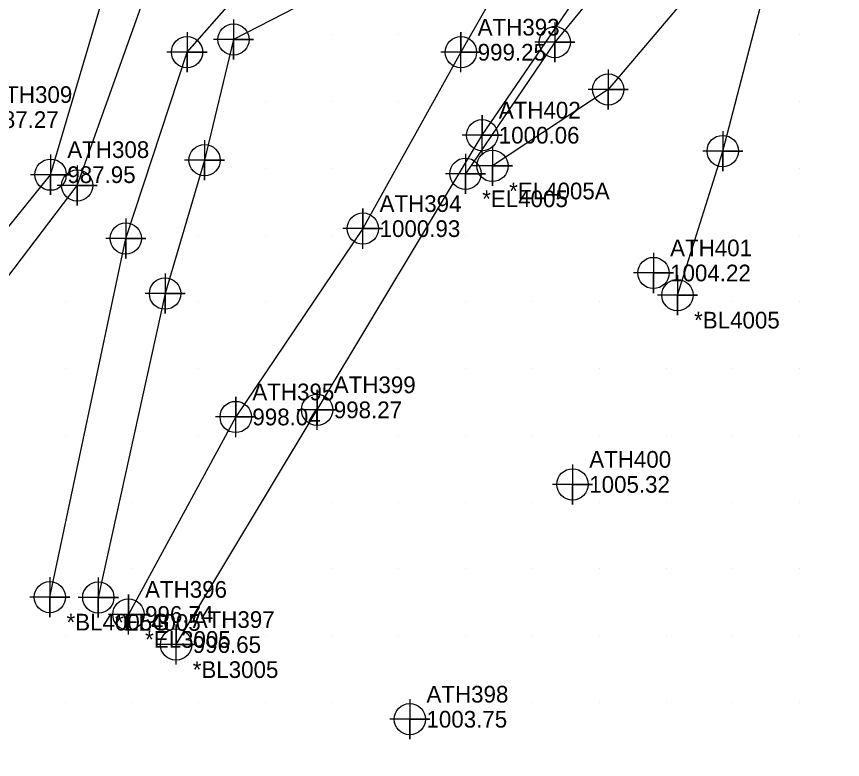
# Model space of a CAD drawing. Extents: x 1116680 to 1117499, y 661040 to 661703.
# Drawn here: x 1117062.7 to 1117186.4, y 661221.5 to 661332.7 of the extents above; entities that cross this region are included whole.
import ezdxf

# ---------------------------------------------------------------- set-up
doc = ezdxf.new("R2010")
doc.units = 0
for name, color, linetype in [('Exist DTM Breakline', 7, 'Continuous'), ('Exist DTM Breakline Cogo Comment', 7, 'Continuous'), ('Exist DTM Breakline Cogo Point CELL', 7, 'Continuous'), ('Exist DTM Drainline Cogo Elevation', 7, 'Continuous'), ('Exist DTM Drainline Cogo Number', 7, 'Continuous'), ('Exist DTM Drainline Cogo Point CELL', 7, 'Continuous'), ('Exist DTM QL2 LIDAR Elevation Point', 7, 'Continuous'), ('Exist DTM Regular Point CELL', 7, 'Continuous'), ('Exist DTM Regular Point Cogo Elevation', 7, 'Continuous'), ('Exist DTM Regular Point Cogo Number', 7, 'Continuous'), ('Exist DTM Regular Point Underwater Cogo Elevation', 7, 'Continuous'), ('Exist DTM Regular Point Underwater Cogo Number', 7, 'Continuous'), ('Exist Hydro Stream or Body of Water', 7, 'Continuous'), ('Exist Roads Soil', 7, 'Continuous'), ('Exist Roads Soil Cogo Comment', 7, 'Continuous'), ('Exist Roads Soil Cogo Elevation', 7, 'Continuous'), ('Exist Roads Soil Cogo Number', 7, 'Continuous'), ('Exist Roads Soil Cogo Point CELL', 7, 'Continuous')]:
    doc.layers.add(name, color=color, linetype=linetype)

msp = doc.modelspace()

# ---------------------------------------------------------------- linework, layer by layer
at = {"layer": 'Exist DTM Breakline'}
for points in [[(1117161.696, 661291.017), (1117168.482, 661312.597), (1117176.266, 661342.559), (1117182.941, 661374.652), (1117194.026, 661386.336), (1117220.943, 661405.14), (1117272.33, 661460.939), (1117291.277, 661496.211), (1117300.472, 661516.498), (1117320.583, 661567.148), (1117342.592, 661626.703), (1117356.346, 661660.105)], [(1117170.247, 661372.296), (1117153.034, 661340.751), (1117143.346, 661328.905), (1117129.964, 661309.196)], [(1117170.843, 661370.689), (1117163.366, 661336.06), (1117151.339, 661321.82), (1117133.997, 661310.363)], [(1117093.445, 661360.799), (1117137.626, 661368.708), (1117143.021, 661357.384), (1117121.473, 661342.844), (1117095.236, 661329.298), (1117090.897, 661311.231), (1117084.978, 661291.24), (1117074.985, 661245.735)], [(1117067.72, 661245.781), (1117079.092, 661299.504), (1117088.264, 661327.406), (1117096.09, 661336.305), (1117116.041, 661346.019), (1117139.594, 661357.628)], [(1117040.467, 661266.201), (1117071.81, 661307.445), (1117084.165, 661341.998)]]:
    msp.add_lwpolyline(points, dxfattribs=at)
at = {"layer": 'Exist DTM Breakline Cogo Point CELL'}
for points in [[(1117095.236, 661332.298), (1117095.236, 661326.298), (1117095.236, 661329.298), (1117098.236, 661329.298), (1117092.236, 661329.298)], [(1117143.346, 661331.905), (1117143.346, 661325.905), (1117143.346, 661328.905), (1117146.346, 661328.905), (1117140.346, 661328.905)], [(1117088.264, 661330.406), (1117088.264, 661324.406), (1117088.264, 661327.406), (1117091.264, 661327.406), (1117085.264, 661327.406)], [(1117151.339, 661324.82), (1117151.339, 661318.82), (1117151.339, 661321.82), (1117154.339, 661321.82), (1117148.339, 661321.82)], [(1117168.482, 661315.597), (1117168.482, 661309.597), (1117168.482, 661312.597), (1117171.482, 661312.597), (1117165.482, 661312.597)], [(1117090.897, 661314.231), (1117090.897, 661308.231), (1117090.897, 661311.231), (1117093.897, 661311.231), (1117087.897, 661311.231)], [(1117133.997, 661313.363), (1117133.997, 661307.363), (1117133.997, 661310.363), (1117136.997, 661310.363), (1117130.997, 661310.363)], [(1117129.964, 661312.196), (1117129.964, 661306.196), (1117129.964, 661309.196), (1117132.964, 661309.196), (1117126.964, 661309.196)], [(1117071.81, 661310.445), (1117071.81, 661304.445), (1117071.81, 661307.445), (1117074.81, 661307.445), (1117068.81, 661307.445)], [(1117079.092, 661302.504), (1117079.092, 661296.504), (1117079.092, 661299.504), (1117082.092, 661299.504), (1117076.092, 661299.504)], [(1117084.978, 661294.24), (1117084.978, 661288.24), (1117084.978, 661291.24), (1117087.978, 661291.24), (1117081.978, 661291.24)], [(1117161.696, 661294.017), (1117161.696, 661288.017), (1117161.696, 661291.017), (1117164.696, 661291.017), (1117158.696, 661291.017)], [(1117067.72, 661248.781), (1117067.72, 661242.781), (1117067.72, 661245.781), (1117070.72, 661245.781), (1117064.72, 661245.781)], [(1117074.985, 661248.735), (1117074.985, 661242.735), (1117074.985, 661245.735), (1117077.985, 661245.735), (1117071.985, 661245.735)]]:
    msp.add_lwpolyline(points, dxfattribs=at)
for centre in [(1117095.236, 661329.298), (1117143.346, 661328.905), (1117088.264, 661327.406), (1117151.339, 661321.82), (1117168.482, 661312.597), (1117090.897, 661311.231), (1117133.997, 661310.363), (1117129.964, 661309.196), (1117071.81, 661307.445), (1117079.092, 661299.504), (1117084.978, 661291.24), (1117161.696, 661291.017), (1117067.72, 661245.781), (1117074.985, 661245.735)]:
    msp.add_circle(centre, 2.344, dxfattribs=at)
at = {"layer": 'Exist DTM Drainline Cogo Point CELL'}
msp.add_lwpolyline([(1117067.842, 661312.057), (1117067.842, 661306.057), (1117067.842, 661309.057), (1117070.842, 661309.057), (1117064.842, 661309.057)], dxfattribs=at)
msp.add_circle((1117067.842, 661309.057), 2.344, dxfattribs=at)
at = {"layer": 'Exist DTM QL2 LIDAR Elevation Point'}
for p, q in [((1117110, 661330), (1117110, 661330)), ((1117120, 661330), (1117120, 661330)), ((1117180, 661330), (1117180, 661330)), ((1117100, 661320), (1117100, 661320)), ((1117110, 661320), (1117110, 661320)), ((1117120, 661320), (1117120, 661320)), ((1117180, 661320), (1117180, 661320)), ((1117080, 661310), (1117080, 661310)), ((1117100, 661310), (1117100, 661310)), ((1117110, 661310), (1117110, 661310)), ((1117180, 661310), (1117180, 661310)), ((1117090, 661300), (1117090, 661300)), ((1117100, 661300), (1117100, 661300)), ((1117110, 661300), (1117110, 661300)), ((1117130, 661300), (1117130, 661300)), ((1117170, 661300), (1117170, 661300)), ((1117180, 661300), (1117180, 661300)), ((1117070, 661290), (1117070, 661290)), ((1117090, 661290), (1117090, 661290)), ((1117100, 661290), (1117100, 661290)), ((1117130, 661290), (1117130, 661290)), ((1117140, 661290), (1117140, 661290)), ((1117150, 661290), (1117150, 661290)), ((1117170, 661290), (1117170, 661290)), ((1117180, 661290), (1117180, 661290)), ((1117070, 661280), (1117070, 661280)), ((1117090, 661280), (1117090, 661280)), ((1117120, 661280), (1117120, 661280)), ((1117130, 661280), (1117130, 661280)), ((1117140, 661280), (1117140, 661280)), ((1117150, 661280), (1117150, 661280)), ((1117160, 661280), (1117160, 661280)), ((1117170, 661280), (1117170, 661280)), ((1117180, 661280), (1117180, 661280)), ((1117070, 661270), (1117070, 661270)), ((1117090, 661270), (1117090, 661270)), ((1117120, 661270), (1117120, 661270)), ((1117130, 661270), (1117130, 661270)), ((1117140, 661270), (1117140, 661270)), ((1117150, 661270), (1117150, 661270)), ((1117160, 661270), (1117160, 661270)), ((1117170, 661270), (1117170, 661270)), ((1117180, 661270), (1117180, 661270)), ((1117080, 661260), (1117080, 661260)), ((1117110, 661260), (1117110, 661260)), ((1117120, 661260), (1117120, 661260)), ((1117130, 661260), (1117130, 661260)), ((1117140, 661260), (1117140, 661260)), ((1117150, 661260), (1117150, 661260)), ((1117160, 661260), (1117160, 661260)), ((1117170, 661260), (1117170, 661260)), ((1117180, 661260), (1117180, 661260)), ((1117080, 661250), (1117080, 661250)), ((1117110, 661250), (1117110, 661250)), ((1117120, 661250), (1117120, 661250)), ((1117130, 661250), (1117130, 661250)), ((1117140, 661250), (1117140, 661250)), ((1117150, 661250), (1117150, 661250)), ((1117160, 661250), (1117160, 661250)), ((1117170, 661250), (1117170, 661250)), ((1117180, 661250), (1117180, 661250)), ((1117070, 661240), (1117070, 661240)), ((1117100, 661240), (1117100, 661240)), ((1117110, 661240), (1117110, 661240)), ((1117120, 661240), (1117120, 661240)), ((1117130, 661240), (1117130, 661240)), ((1117140, 661240), (1117140, 661240)), ((1117150, 661240), (1117150, 661240)), ((1117160, 661240), (1117160, 661240)), ((1117170, 661240), (1117170, 661240)), ((1117180, 661240), (1117180, 661240)), ((1117070, 661230), (1117070, 661230)), ((1117080, 661230), (1117080, 661230)), ((1117090, 661230), (1117090, 661230)), ((1117100, 661230), (1117100, 661230)), ((1117110, 661230), (1117110, 661230)), ((1117120, 661230), (1117120, 661230)), ((1117130, 661230), (1117130, 661230)), ((1117140, 661230), (1117140, 661230)), ((1117150, 661230), (1117150, 661230)), ((1117160, 661230), (1117160, 661230)), ((1117170, 661230), (1117170, 661230)), ((1117180, 661230), (1117180, 661230))]:
    msp.add_line(p, q, dxfattribs=at)
at = {"layer": 'Exist DTM Regular Point CELL'}
for points in [[(1117158.105, 661297.331), (1117158.105, 661291.331), (1117158.105, 661294.331), (1117161.105, 661294.331), (1117155.105, 661294.331)], [(1117145.994, 661265.665), (1117145.994, 661259.665), (1117145.994, 661262.665), (1117148.994, 661262.665), (1117142.994, 661262.665)], [(1117121.622, 661230.488), (1117121.622, 661224.488), (1117121.622, 661227.488), (1117124.622, 661227.488), (1117118.622, 661227.488)]]:
    msp.add_lwpolyline(points, dxfattribs=at)
for centre in [(1117158.105, 661294.331), (1117145.994, 661262.665), (1117121.622, 661227.488)]:
    msp.add_circle(centre, 2.344, dxfattribs=at)
at = {"layer": 'Exist Hydro Stream or Body of Water'}
msp.add_lwpolyline([(1116999.252, 661212.663), (1117035.553, 661269.03), (1117067.842, 661309.057), (1117080.473, 661351.773), (1117079.751, 661359.687), (1117095.986, 661391.983), (1117110.725, 661432.453), (1117125.362, 661468.034)], dxfattribs=at)
at = {"layer": 'Exist Roads Soil'}
for points in [[(1117086.62, 661238.672), (1117107.742, 661273.834), (1117132.451, 661314.97), (1117148.912, 661339.084), (1117167.138, 661380.575)], [(1117137.718, 661372.755), (1117145.395, 661365.554), (1117144.424, 661353.972), (1117129.288, 661327.396), (1117114.601, 661300.973), (1117095.553, 661272.762), (1117079.487, 661243.188)]]:
    msp.add_lwpolyline(points, dxfattribs=at)
at = {"layer": 'Exist Roads Soil Cogo Point CELL'}
for points in [[(1117129.288, 661324.396), (1117129.288, 661330.396), (1117129.288, 661327.396), (1117132.288, 661327.396), (1117126.288, 661327.396)], [(1117132.451, 661311.97), (1117132.451, 661317.97), (1117132.451, 661314.97), (1117135.451, 661314.97), (1117129.451, 661314.97)], [(1117114.601, 661297.973), (1117114.601, 661303.973), (1117114.601, 661300.973), (1117117.601, 661300.973), (1117111.601, 661300.973)], [(1117107.742, 661270.834), (1117107.742, 661276.834), (1117107.742, 661273.834), (1117110.742, 661273.834), (1117104.742, 661273.834)], [(1117095.553, 661269.762), (1117095.553, 661275.762), (1117095.553, 661272.762), (1117098.553, 661272.762), (1117092.553, 661272.762)], [(1117079.487, 661240.188), (1117079.487, 661246.188), (1117079.487, 661243.188), (1117082.487, 661243.188), (1117076.487, 661243.188)], [(1117086.62, 661235.672), (1117086.62, 661241.672), (1117086.62, 661238.672), (1117089.62, 661238.672), (1117083.62, 661238.672)]]:
    msp.add_lwpolyline(points, dxfattribs=at)
for centre in [(1117129.288, 661327.396), (1117132.451, 661314.97), (1117114.601, 661300.973), (1117107.742, 661273.834), (1117095.553, 661272.762), (1117079.487, 661243.188), (1117086.62, 661238.672)]:
    msp.add_circle(centre, 2.344, dxfattribs=at)

# ---------------------------------------------------------------- texts
at = {"layer": 'Exist DTM Breakline Cogo Comment'}
for s, p in [('*EL4005A', (1117136.497, 661305.363)), ('*EL4005', (1117132.464, 661304.196)), ('*BL4005', (1117164.196, 661286.017)), ('*BL4005G', (1117070.22, 661240.781)), ('*EL4005', (1117077.485, 661240.735))]:
    msp.add_text(s, height=2.5, dxfattribs=at).set_placement(p)
at = {"layer": 'Exist DTM Drainline Cogo Elevation'}
msp.add_text('987.95', height=2.5, dxfattribs=at).set_placement((1117070.342, 661307.807))
at = {"layer": 'Exist DTM Drainline Cogo Number'}
msp.add_text('ATH308', height=2.5, dxfattribs=at).set_placement((1117070.342, 661311.557))
at = {"layer": 'Exist DTM Regular Point Cogo Elevation'}
for s, p in [('1004.22', (1117160.605, 661293.081)), ('1005.32', (1117148.494, 661261.415)), ('1003.75', (1117124.122, 661226.238))]:
    msp.add_text(s, height=2.5, dxfattribs=at).set_placement(p)
at = {"layer": 'Exist DTM Regular Point Cogo Number'}
for s, p in [('ATH401', (1117160.605, 661296.831)), ('ATH400', (1117148.494, 661265.165)), ('ATH398', (1117124.122, 661229.988))]:
    msp.add_text(s, height=2.5, dxfattribs=at).set_placement(p)
at = {"layer": 'Exist DTM Regular Point Underwater Cogo Elevation'}
msp.add_text('987.27', height=2.5, dxfattribs=at).set_placement((1117058.82, 661316.051))
at = {"layer": 'Exist DTM Regular Point Underwater Cogo Number'}
msp.add_text('ATH309', height=2.5, dxfattribs=at).set_placement((1117058.82, 661319.801))
at = {"layer": 'Exist Roads Soil Cogo Comment'}
for s, p in [('*EL3005', (1117081.987, 661238.188)), ('*BL3005', (1117089.12, 661233.672))]:
    msp.add_text(s, height=2.5, dxfattribs=at).set_placement(p)
at = {"layer": 'Exist Roads Soil Cogo Elevation'}
for s, p in [('999.25', (1117131.788, 661326.146)), ('1000.06', (1117134.951, 661313.72)), ('1000.93', (1117117.101, 661299.723)), ('998.27', (1117110.242, 661272.584)), ('998.04', (1117098.053, 661271.512)), ('996.74', (1117081.987, 661241.938)), ('996.65', (1117089.12, 661237.422))]:
    msp.add_text(s, height=2.5, dxfattribs=at).set_placement(p)
at = {"layer": 'Exist Roads Soil Cogo Number'}
for s, p in [('ATH393', (1117131.788, 661329.896)), ('ATH402', (1117134.951, 661317.47)), ('ATH394', (1117117.101, 661303.473)), ('ATH399', (1117110.242, 661276.334)), ('ATH395', (1117098.053, 661275.262)), ('ATH396', (1117081.987, 661245.688)), ('ATH397', (1117089.12, 661241.172))]:
    msp.add_text(s, height=2.5, dxfattribs=at).set_placement(p)

doc.saveas('drawing.dxf')
